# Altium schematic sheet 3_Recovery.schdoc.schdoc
size 309 x 223 mm; Symbol: Sheet-Symbol_A4; Device: Sheet-Symbol_A4; Company: EasyEDA.com; Drawed: EasyEDA Pro; Reviewed: EasyEDA Pro; Version: V2.3; Page Size: A4; @Project Name: RecoveryBoard_W24Edits; @Page Count: 3; @Update Date: 2024-04-04; @Create Date: 2024-01-31; @Schematic Name: Schematic; Part Number: JLCPCB-002; @Page No: 2; @Page Name: Recovery
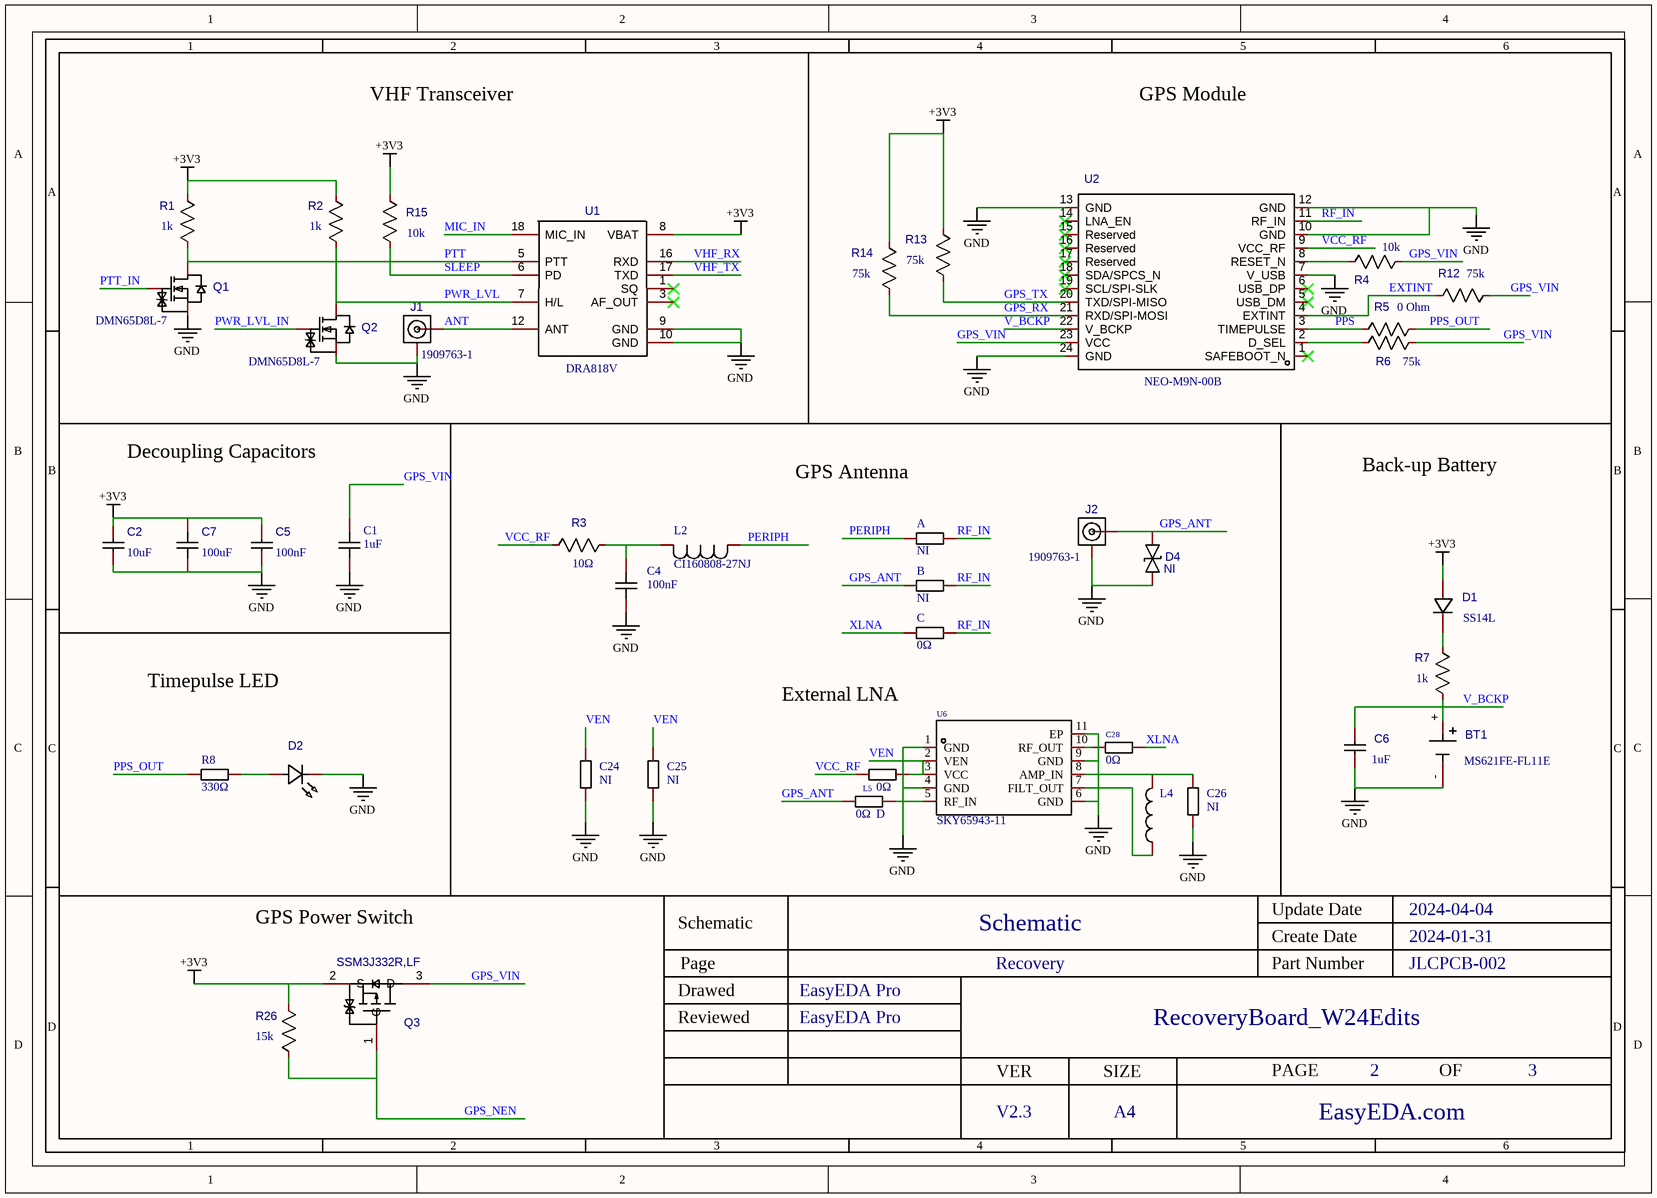
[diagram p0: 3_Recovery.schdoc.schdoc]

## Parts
A  NI  [R0402]
B  NI  [R0402]
BT1  MS621FE-FL11E  [MS621FE-FL11E]
C  0Ω  [R0402]
C1  1uF  [C0402]
C2  10uF  [C0603]
C4  100nF  [C0402]
C5  100nF  [C0402]
C6  1uF  [C0402]
C7  100uF  [C1210]
C24  NI  [R0402]
C25  NI  [R0402]
C26  NI  [R0402]
C28  0Ω  [R0402]
D  0Ω  [R0402]
D1  SS14L  [SMA_L4.4-W2.6-LS5.0-RD]
D2  16-213/BHC-ZL1M2B6Y/3T  [LED0402-RD_BLUE]  (value not drawn)
D4  NI  [SOD-323_L1.8-W1.3-LS2.5-BI]
J1  1909763-1  [ANT-SMD_1909763-1]
J2  1909763-1  [ANT-SMD_1909763-1]
L2  CI160808-27NJ  [IND_BOURNS_CI160808]
L4  LQW15AN9N1J00D_  [INDC1006X60N]  (value not drawn)
L5  0Ω  [R0402]
Q1  DMN65D8L-7  [SOT-23-3_L3.0-W1.7-P0.95-LS2.9-BR]
Q2  DMN65D8L-7  [SOT-23-3_L3.0-W1.7-P0.95-LS2.9-BR]
Q3  SSM3J332R,LF  [SOT-23F_L2.9-W1.8-P0.95-LS2.4-BR]
R1  1k  [R0603]
R2  1k  [R0603]
R3  10Ω  [R0603]
R4  10k  [R0603]
R5  0 Ohm  [R0603]
R6  75k  [R0603]
R7  1k  [R0603]
R8  330Ω  [R0603]
R12  75k  [R0603]
R13  75k  [R0603]
R14  75k  [R0603]
R15  10k  [R0603]
R26  15k  [R0402]
U1  DRA818V  [DORJI_DRA818V]
U2  NEO-M9N-00B  [GPSM-SMD_24P-L16.0-W12.2-P1.10-BL]
U6  SKY65943-11  [MCM-10_L2.5-W2.5-P0.50-BL-EP]

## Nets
+3V3: C2.2 C5.2 C7.1 D1.2(A) Q3.2(S) R1.2 R2.2 R13.2 R14.2 R15.2 R26.2 U1.8(VBAT)
GND: BT1.- C1.1 C2.1 C4.1 C5.1 C6.1 C7.2 C24.1 C25.1 C26.1 D2.1(K) D4.1 J1.2 J2.2 Q1.2(S) Q2.2(S) U1.9(GND) U1.10(GND) U2.7(V_USB) U2.10(GND) U2.12(GND) U2.13(GND) U2.24(GND) U6.1(GND) U6.4(GND) U6.6(GND) U6.9(GND) U6.11(EP)
ANT: J1.1 U1.12(ANT)
EXTINT: R12.1 U2.4(EXTINT)
GPS_ANT: B.1 D.1 D4.2 J2.1
GPS_NEN: Q3.1(G) R26.1
GPS_RX: R14.1 U2.21(RXD/SPI-MOSI)
GPS_TX: R13.1 U2.20(TXD/SPI-MISO)
GPS_VIN: C1.2 Q3.3(D) R4.2 R6.2 R12.2 U2.23(VCC)
MIC_IN: U1.18(MIC_IN)
PERIPH: A.1 L2.2
PPS: R5.1 U2.3(TIMEPULSE)
PPS_OUT: R5.2 R8.1
PTT: Q1.3(D) R1.1 U1.5(PTT)
PTT_IN: Q1.1(G)
PWR_LVL: Q2.3(D) R2.1 U1.7(H/L)
PWR_LVL_IN: Q2.1(G)
RF_IN: A.2 B.2 C.2 U2.11(RF_IN)
SLEEP: R15.1 U1.6(PD)
V_BCKP: BT1.+ C6.2 R7.1 U2.22(V_BCKP)
VCC_RF: L5.1 R3.1 U2.9(VCC_RF)
VEN: C24.2 C25.2 L5.2 U6.2(VEN) U6.3(VCC)
VHF_RX: U1.16(RXD)
VHF_TX: U1.17(TXD)
XLNA: C.1 C28.2
NetC4_2: C4.2 L2.1 R3.2
NetC26_2: C26.2 L4.2 U6.8(AMP_IN)
NetC28_1: C28.1 U6.10(RF_OUT)
NetD1_1: D1.1(C) R7.2
NetD2_2: D2.2(A) R8.2
NetD_2: D.2 U6.5(RF_IN)
NetL4_1: L4.1 U6.7(FILT_OUT)
NetR4_1: R4.1 U2.8(RESET_N)
NetR6_1: R6.1 U2.2(D_SEL)

Not connected (* = marked no-connect by the designer): U1 1(SQ)* 3(AF_OUT)*; U2 1(SAFEBOOT_N)* 5(USB_DM)* 6(USB_DP)* 14(LNA_EN)* 15(Reserved)* 16(Reserved)* 17(Reserved)* 18(SDA/SPCS_N)* 19(SCL/SPI-SLK)*

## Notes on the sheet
- VHF Transceiver
- GPS Module
- Decoupling Capacitors
- Back-up Battery
- GPS Antenna
- Timepulse LED
- External LNA
- GPS Power Switch

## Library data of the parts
A B C24-C26 = ERJ2GE0R00X: Type:Thick Film Resistors Resistance: Power(Watts): Overload Voltage (Max):- Temperature Coefficient:-100ppm/℃~+600ppm/℃ Temperature Coefficient:-100ppm/℃~+600ppm/℃ Operating Temperature Range:-55℃~+155℃ Operating Temperature Range:-55℃~+155℃; Manufacturer: PANASONIC(松下); Add into BOM: no; Convert to PCB: yes
BT1 = MS621FE-FL11E: Convert to PCB: yes; Origin Footprint: BAT_MS621FE-FL11E
C = ERJ2GE0R00X: Type:Thick Film Resistors Resistance: Power(Watts): Overload Voltage (Max):- Temperature Coefficient:-100ppm/℃~+600ppm/℃ Temperature Coefficient:-100ppm/℃~+600ppm/℃ Operating Temperature Range:-55℃~+155℃ Operating Temperature Range:-55℃~+155℃; Manufacturer: PANASONIC(松下); Add into BOM: yes
C1 = CC0402KRX5R7BB105: Manufacturer: YAGEO(国巨); Add into BOM: yes; Tolerance: ±10%; Description: Capacitance: Tolerance:±10% Tolerance:±10% Voltage Rated: Temperature Coefficient:
C2 = GRM188R60G106ME47D: Manufacturer: muRata(村田); Convert to PCB: yes; Check: true
C4 = GCM155R71C104KA55J: Manufacturer: muRata(村田); Add into BOM: yes; Tolerance: ±10%; Description: Capacitance: Tolerance:±10% Tolerance:±10% Voltage Rated: Temperature Coefficient:
C5 = CC0402ZRY5V7BB104: Manufacturer: YAGEO(国巨); Convert to PCB: yes
C6 = GRM155R61E105KA12D: Manufacturer: muRata(村田); Convert to PCB: yes
C7 = GRM32ER60J107ME20L: Manufacturer: muRata(村田); Convert to PCB: yes
C28 L5 = ERJ2GE0R00X: Manufacturer: PANASONIC(松下); Add into BOM: yes; Type: Thick Film Resistors; Temperature Coefficient: -100ppm/℃~+600ppm/℃; Description: Type:Thick Film Resistors Resistance: Power(Watts): Overload Voltage (Max):- Temperature Coefficient:-100ppm/℃~+600ppm/℃ Temperature Coefficient:-100ppm/℃~+600ppm/℃ Operating Temperature Range:-55℃~+155℃ Operating Temperature Range:-55℃~+155℃
D = ERJ2GE0R00X: Manufacturer: PANASONIC(松下); Add into BOM: yes; Temperature Coefficient: -100ppm/℃~+600ppm/℃; Description: Type:Thick Film Resistors Resistance: Power(Watts): Overload Voltage (Max):- Temperature Coefficient:-100ppm/℃~+600ppm/℃ Temperature Coefficient:-100ppm/℃~+600ppm/℃ Operating Temperature Range:-55℃~+155℃ Operating Temperature Range:-55℃~+155℃
D1 = SS14L_R1_00001: Manufacturer: PANJIT(强茂); Convert to PCB: yes
D2 = 16-213/BHC-ZL1M2B6Y/3T: Manufacturer: EVERLIGHT(亿光); Convert to PCB: yes
D4 = LESD3Z5.0CMT1G: Manufacturer: LRC(乐山无线电); Convert to PCB: yes; Add into BOM: no
J1 J2 = 1909763-1: Manufacturer: TEConnectivity(美国泰科); Convert to PCB: yes
L2 = CI160808-27NJ_IND_BOURNS_CI160808: Add into BOM: yes
L4 = LQW15AN9N1J00D_: Add into BOM: yes
Q1 Q2 = DMN65D8L-7: Manufacturer: DIODES(美台); Convert to PCB: yes
Q3 = SSM3J332R,LF: Manufacturer: TOSHIBA; Add into BOM: yes
R1 R2 R7 = 1k: Convert to PCB: yes
R3 = ESR03EZPJ100: Type:Thick Film Resistors Resistance: Tolerance:±5% Tolerance:±5% Power(Watts):250mW Overload Voltage (Max): Temperature Coefficient:±200ppm/℃ Temperature Coefficient:±200ppm/℃ Operating Temperature Range:-55℃~+155℃ Operating Temperature Range:-55℃~+155℃; Manufacturer: ROHM(罗姆); Symbol: 10; Add into BOM: yes; Tolerance: ±5%; Power(Watts): 250mW
R4 R15 = RC0603FR-0710KL: Convert to PCB: yes
R5 = 0603WAF0000T5E: Convert to PCB: yes
R6 R12-R14 = RC0603FR-0775KL: Convert to PCB: yes
R8 = RC0603JR-07330RL: Manufacturer: YAGEO(国巨); Add into BOM: yes; Tolerance: ±5%; Temperature Coefficient: ±100ppm/℃; Description: Type:Thick Film Resistors Resistance: Tolerance:±5% Tolerance:±5% Power(Watts): Overload Voltage (Max): Temperature Coefficient:±100ppm/℃ Temperature Coefficient:±100ppm/℃ Operating Temperature Range:-55℃~+155℃ Operating Temperature Range:-55℃~+155℃
R26 = RC0603FR-0710RL: Manufacturer Part: 0402WGF1502TCE; Symbol: 10; Convert to PCB: yes
U1 = DRA818V: Convert to PCB: yes
U2 = NEO-M9N-00B: Manufacturer: null; Convert to PCB: yes
U6 = SKY65943-11: Manufacturer: SKYWORKS; Add into BOM: yes; Frequency Range: 1.559GHz~1.606GHz; Description: Frequency Range:1.559GHz~1.606GHz Frequency Range:1.559GHz~1.606GHz Applications:Galileo,GLONASS,GNSS,GPS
